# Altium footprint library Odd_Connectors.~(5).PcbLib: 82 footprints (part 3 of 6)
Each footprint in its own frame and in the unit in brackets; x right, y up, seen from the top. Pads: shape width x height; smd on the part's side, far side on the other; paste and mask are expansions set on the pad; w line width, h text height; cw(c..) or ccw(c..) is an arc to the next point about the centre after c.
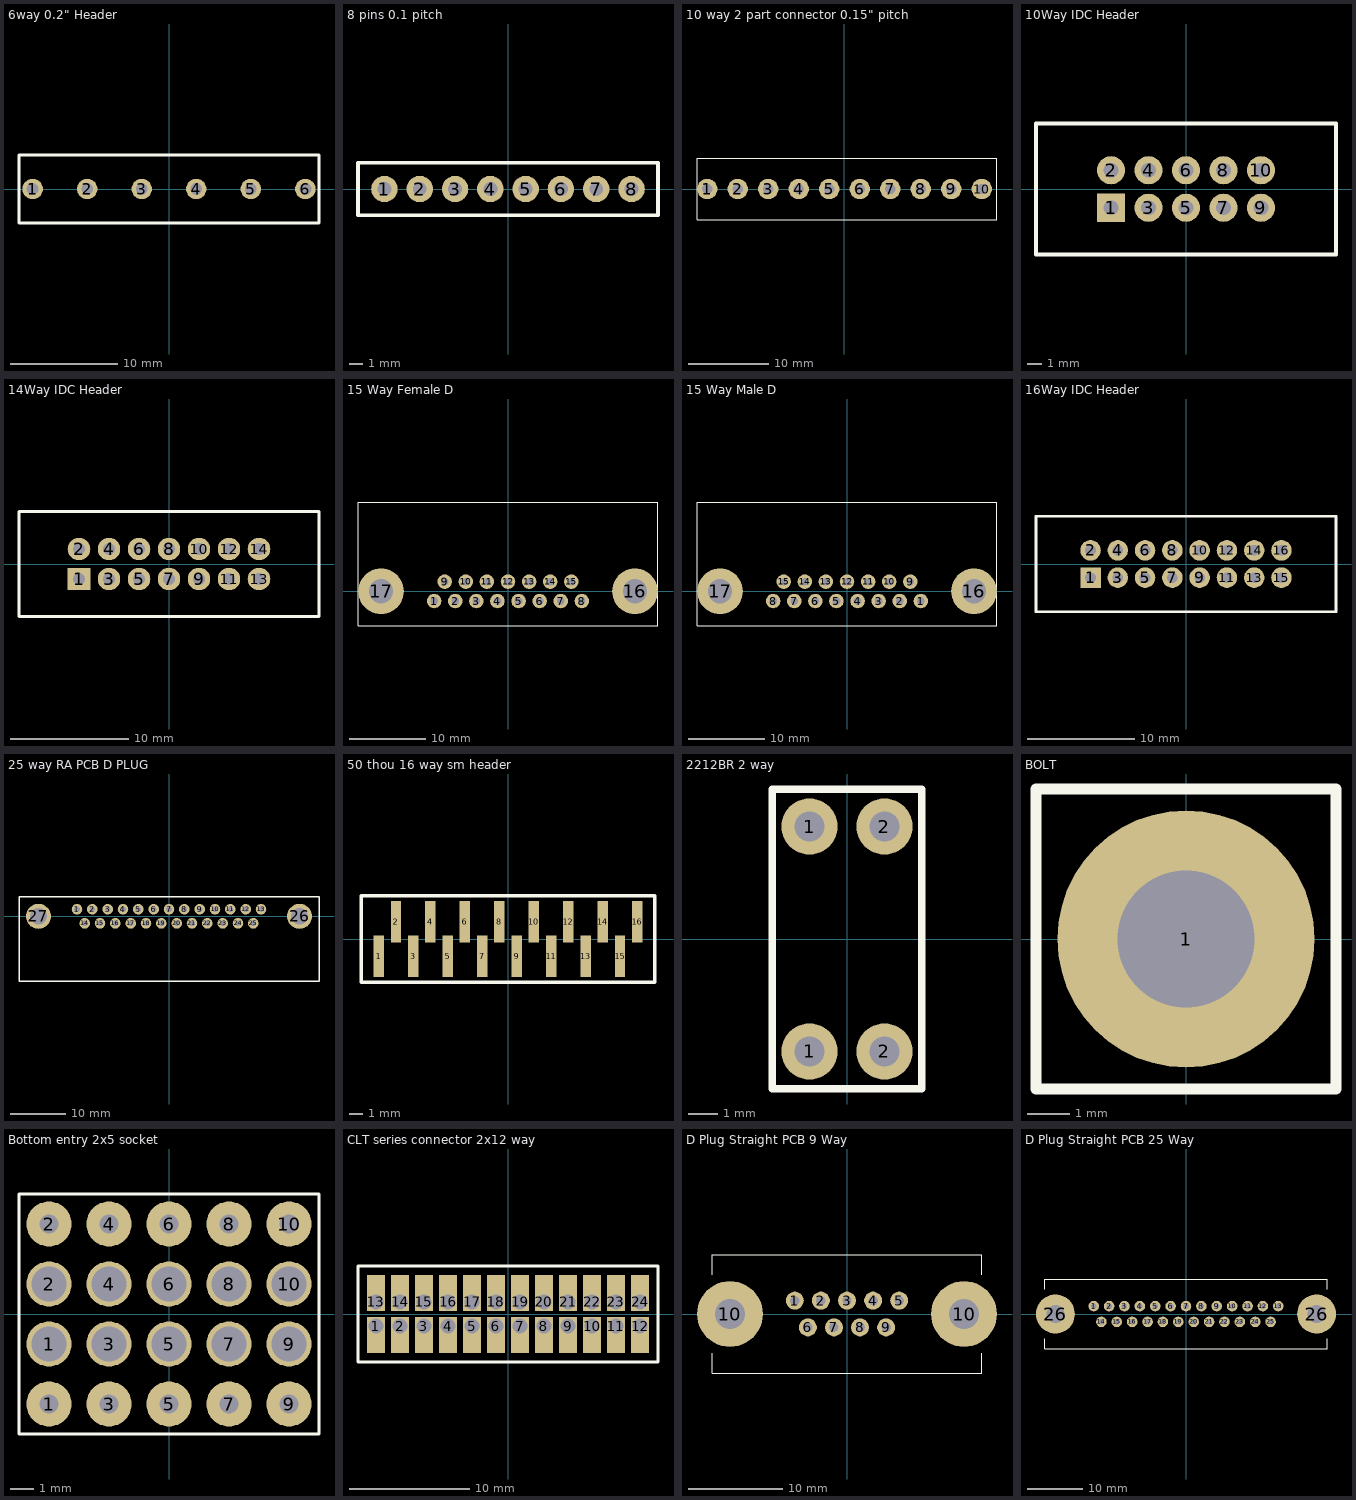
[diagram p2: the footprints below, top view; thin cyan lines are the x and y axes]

## 6way 0.2" Header [mm] "Header with big gaps between the pins!"
pads (6):
  round 1.905 hole 1.1: 1(-12.7,0) 2(-7.62,0) 3(-2.54,0) 4(2.54,0) 5(7.62,0) 6(12.7,0)
Top Overlay:
  lines w0.254: -13.97,-3.175 13.97,-3.175 13.97,3.175 -13.97,3.175 -13.97,-3.175

## 8 pins 0.1 pitch [mm] "pin header"
height 12
pads (8):
  round 1.905 hole 1: 1(-8.89,0) 2(-6.35,0) 3(-3.81,0) 4(-1.27,0) 5(1.27,0) 6(3.81,0) 7(6.35,0) 8(8.89,0)
Top Overlay:
  lines w0.254: -10.795,-1.905 -10.795,1.905 10.795,1.905 10.795,-1.905 -10.795,-1.905

## 10 way 2 part connector 0.15" pitch [mm] "10 way connector or terminal block - 0.15\" pitch"
height 10.16
pads (10):
  round 2.54 hole 1.3 unplated: 1(-17.145,0) 2(-13.335,0) 3(-9.525,0) 4(-5.715,0) 5(-1.905,0) 6(1.905,0) 7(5.715,0) 8(9.525,0) 9(13.335,0) 10(17.145,0)
Top Overlay:
  lines w0.025: -18.415,-3.81 19.05,-3.81 19.05,3.81 -18.415,3.81 -18.415,-3.81

## 10Way IDC Header [mm]
height 10
pads (10):
  rect 1.905x1.905 hole 1: 1(-5.08,-1.27)
  round 1.905 hole 1: 2(-5.08,1.27) 3(-2.54,-1.27) 4(-2.54,1.27) 5(0,-1.27) 6(0,1.27) 7(2.54,-1.27) 8(2.54,1.27) 9(5.08,-1.27) 10(5.08,1.27)
Top Overlay:
  lines w0.254: -10.16,-4.445 10.16,-4.445 10.16,4.445 -10.16,4.445 -10.16,-4.445

## 14Way IDC Header [mm]
height 10
pads (14):
  rect 1.905x1.905 hole 1: 1(-7.62,-1.27)
  round 1.905 hole 1: 2(-7.62,1.27) 3(-5.08,-1.27) 4(-5.08,1.27) 5(-2.54,-1.27) 6(-2.54,1.27) 7(0,-1.27) 8(0,1.27) 9(2.54,-1.27) 10(2.54,1.27) 11(5.08,-1.27) 12(5.08,1.27) 13(7.62,-1.27) 14(7.62,1.27)
Top Overlay:
  lines w0.254: -12.7,-4.445 -12.7,4.445 12.7,4.445 12.7,-4.445 -12.7,-4.445

## 15 Way Female D [mm] "RA PCB mounted D connector"
height 11.5
pads (17):
  round 1.905 hole 1: 1(-9.69,-1.27) 2(-6.921,-1.27) 3(-4.153,-1.27) 4(-1.385,-1.27) 5(1.385,-1.27) 6(4.155,-1.27) 7(6.925,-1.27) 8(9.695,-1.27) 9(-8.306,1.275) 10(-5.537,1.275) 11(-2.769,1.275) 12(0,1.27) 13(2.77,1.27) 14(5.54,1.27) 15(8.31,1.27)
  round 6 hole 3.2: 16(16.66,0) 17(-16.66,0)
Top Overlay:
  lines w0.127: -19.685,-4.5 19.685,-4.5 19.685,11.675 -19.685,11.675 -19.685,-4.5

## 15 Way Male D [mm] "RA PCB mounted D connector"
height 11.5
pads (17):
  round 1.905 hole 1: 1(9.695,-1.27) 2(6.925,-1.27) 3(4.155,-1.27) 4(1.385,-1.27) 5(-1.385,-1.27) 6(-4.153,-1.27) 7(-6.921,-1.27) 8(-9.69,-1.27) 9(8.31,1.27) 10(5.54,1.27) 11(2.77,1.27) 12(0,1.27) 13(-2.769,1.275) 14(-5.537,1.275) 15(-8.306,1.275)
  round 6 hole 3.2: 16(16.66,0) 17(-16.66,0)
Top Overlay:
  lines w0.127: -19.685,-4.5 19.685,-4.5 19.685,11.675 -19.685,11.675 -19.685,-4.5

## 16Way IDC Header [mm]
height 10
pads (16):
  rect 1.905x1.905 hole 1: 1(-8.89,-1.27)
  round 1.905 hole 1: 2(-8.89,1.27) 3(-6.35,-1.27) 4(-6.35,1.27) 5(-3.81,-1.27) 6(-3.81,1.27) 7(-1.27,-1.27) 8(-1.27,1.27) 9(1.27,-1.27) 10(1.27,1.27) 11(3.81,-1.27) 12(3.81,1.27) 13(6.35,-1.27) 14(6.35,1.27) 15(8.89,-1.27) 16(8.89,1.27)
Top Overlay:
  lines w0.254: -13.97,-4.445 -13.97,4.445 13.97,4.445 13.97,-4.445 -13.97,-4.445

## 25 way RA PCB D PLUG [mm] "Harting data used"
height 12.5
pads (27):
  round 1.905 hole 1: 1(-16.56,1.27) 2(-13.8,1.27) 3(-11.04,1.27) 4(-8.28,1.27) 5(-5.52,1.27) 6(-2.76,1.27) 7(0,1.27) 8(2.76,1.27) 9(5.52,1.27) 10(8.28,1.27) 11(11.04,1.27) 12(13.8,1.27) 13(16.56,1.27) 14(-15.18,-1.27) 15(-12.42,-1.27) 16(-9.66,-1.27) 17(-6.9,-1.27) 18(-4.14,-1.27) 19(-1.38,-1.27) 20(1.38,-1.27) 21(4.14,-1.27) 22(6.9,-1.27) 23(9.66,-1.27) 24(12.42,-1.27) 25(15.18,-1.27)
  round 4.5 hole 3: 26(23.5,0) 27(-23.5,0)
Top Overlay:
  lines w0.254: -27,-11.67 -27,3.5 27,3.5 27,-11.67 -27,-11.67

## 50 thou 16 way sm header [mil] "50 thou 16 way sm header"
height 314.96
pads (16):
  rect 30x120 smd: 1(-375,-50) 2(-325,50) 3(-275,-50) 4(-225,50) 5(-175,-50) 6(-125,50) 7(-75,-50) 8(-25,50) 9(25,-50) 10(75,50) 11(125,-50) 12(175,50) 13(225,-50) 14(275,50) 15(325,-50) 16(375,50)
Top Overlay:
  lines w10: -425,-125 425,-125 425,125 -425,125 -425,-125

## 2212BR 2 way [mm] "0.1\" pitch PCB RA Sockets"
pads (4):
  round 1.905 hole 1: 1(-1.27,-3.81) 1(-1.27,3.81) 2(1.27,-3.81) 2(1.27,3.81)
Top Overlay:
  lines w0.254: -2.54,-5.08 2.54,-5.08 2.54,5.08 -2.54,5.08 -2.54,-5.08

## BOLT [mm] "M3 mounting bolt"
height 5
pads (1):
  round 6 hole 3.2: 1(0,0)
Top Overlay:
  lines w0.254: -3.5,-3.5 -3.5,3.5 3.5,3.5 3.5,-3.5 -3.5,-3.5

## Bottom entry 2x5 socket [mm] "Board to board connector, bottom entry, 2x5 way"
height 7
pads (20):
  round 1.905 hole 0.8: 1(-5.08,-3.81) 2(-5.08,3.81) 3(-2.54,-3.81) 4(-2.54,3.81) 5(0,-3.81) 6(0,3.81) 7(2.54,-3.81) 8(2.54,3.81) 9(5.08,-3.81) 10(5.08,3.81)
  round 1.905 hole 1.5: 1(-5.08,-1.27) 2(-5.08,1.27) 3(-2.54,-1.27) 4(-2.54,1.27) 5(0,-1.27) 6(0,1.27) 7(2.54,-1.27) 8(2.54,1.27) 9(5.08,-1.27) 10(5.08,1.27)
Top Overlay:
  lines w0.127: -6.35,-5.08 6.35,-5.08 6.35,5.08 -6.35,5.08 -6.35,-5.08

## CLT series connector 2x12 way [mm] "Samtec CLT low profile SM connector"
height 2.13
pads (24):
  rect 1.5x3 hole 1.22 copper offset 0,-0.75: 1(-11,-1) 2(-9,-1) 3(-7,-1) 4(-5,-1) 5(-3,-1) 6(-1,-1) 7(1,-1) 8(3,-1) 9(5,-1) 10(7,-1) 11(9,-1) 12(11,-1)
  rect 1.5x3 hole 1.22 copper offset 0,0.75: 13(-11,1) 14(-9,1) 15(-7,1) 16(-5,1) 17(-3,1) 18(-1,1) 19(1,1) 20(3,1) 21(5,1) 22(7,1) 23(9,1) 24(11,1)
Top Overlay:
  lines w0.254: -12.5,-4 12.5,-4 12.5,4 -12.5,4 -12.5,-4

## D Plug Straight PCB 9 Way [mil] "D Plug Straight PCB 9 Way"
height 472.44
pads (11):
  round 75 hole 39.37 unplated: 1(-218,56) 2(-109,56) 3(0,56) 4(109,56) 5(218,56) 6(-163.5,-56) 7(-54.5,-56) 8(54.5,-56) 9(163.5,-56)
  round 275.59 hole 125.98 unplated: 10(-489,0) 10(489,0)
Top Overlay:
  lines w0.98: -564,-247.05 -564,-164 ; -564,164 -564,247.05 ; 564,-247.05 564,-164 ; 564,164 564,247.05
  lines w1: -564,-247.05 564,-247.05 ; -564,247.05 564,247.05

## D Plug Straight PCB 25 Way [mil] "D Plug Straight PCB 25 Way"
height 472.44
pads (27):
  round 75 hole 39.37 unplated: 1(-654,56) 2(-545,56) 3(-436,56) 4(-327,56) 5(-218,56) 6(-109,56) 7(0,56) 8(109,56) 9(218,56) 10(327,56) 11(436,56) 12(545,56) 13(654,56) 14(-599.5,-56) 15(-490.5,-56) 16(-381.5,-56) 17(-272.5,-56) 18(-163.5,-56) 19(-54.5,-56) 20(54.5,-56) 21(163.5,-56) 22(272.5,-56) 23(381.5,-56) 24(490.5,-56) 25(599.5,-56)
  round 275.59 hole 125.98 unplated: 26(-925,0) 26(925,0)
Top Overlay:
  lines w0.98: -1000,-247.05 -1000,-175 ; -1000,175 -1000,247.05 ; 1000,-247.05 1000,-175 ; 1000,175 1000,247.05
  lines w1: -1000,-247.05 1000,-247.05 ; -1000,247.05 1000,247.05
